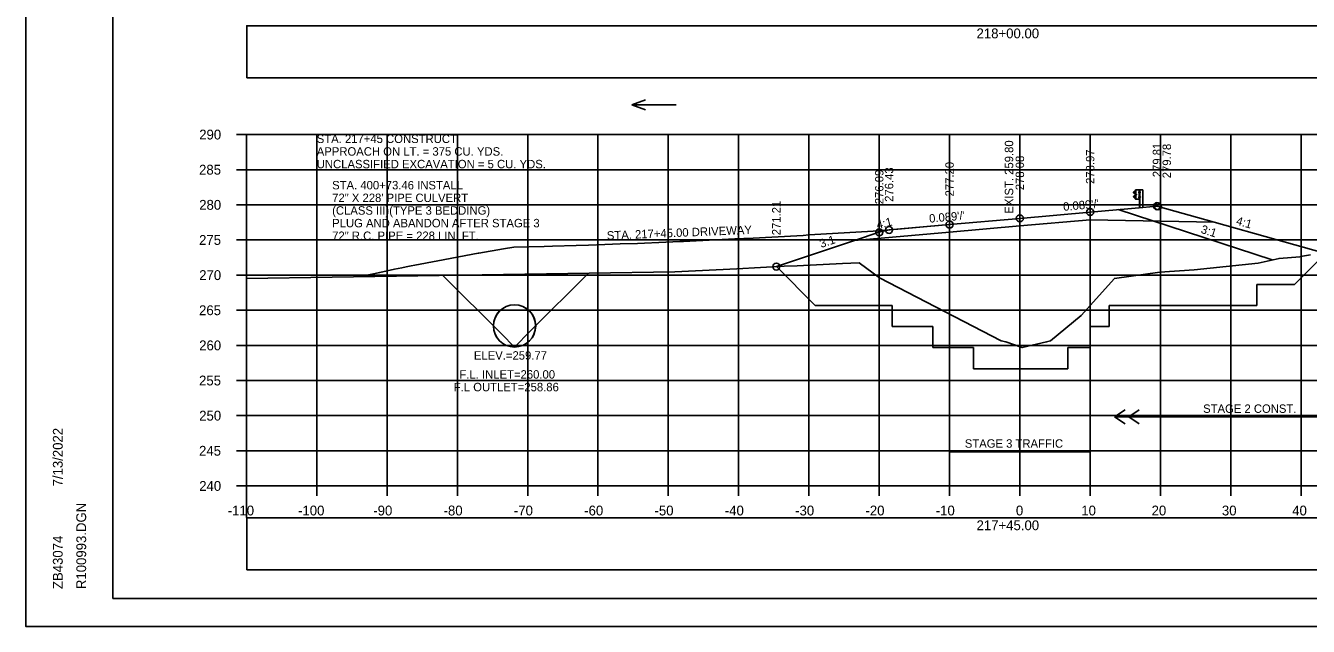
# Model space of a CAD drawing. Extents: x 4667 to 1632277, y -2100 to 724501.
# Drawn here: x 5635.8 to 5818.2, y -1110.4 to -1024.9 of the extents above; entities that cross this region are included whole.
import ezdxf

# ---------------------------------------------------------------- set-up
doc = ezdxf.new("R2010")
doc.units = 0
for name, color, linetype in [('R_Alt Surface', 7, 'Continuous'), ('R_Axis', 7, 'Continuous'), ('R_Axis Annot', 7, 'Continuous'), ('R_Border', 7, 'Continuous'), ('R_Draft', 7, 'Continuous'), ('R_Drive', 7, 'Continuous'), ('R_Exist Surface', 7, 'Continuous'), ('R_Fin Surface', 7, 'Continuous'), ('R_Fin Surface Annot', 7, 'Continuous'), ('R_Grid', 7, 'Continuous'), ('R_No Plot', 7, 'Continuous'), ('R_Proposed CofA', 7, 'Continuous'), ('R_ROW', 7, 'Continuous'), ('R_Temp Easement', 7, 'Continuous'), ('R_Water', 7, 'Continuous'), ('R_Water Annot', 7, 'Continuous'), ('R_Xsect Elev', 7, 'Continuous')]:
    doc.layers.add(name, color=color, linetype=linetype)

msp = doc.modelspace()

# ---------------------------------------------------------------- linework, layer by layer
at = {"layer": 'R_Alt Surface'}
msp.add_lwpolyline([(5753.67, -1055.51), (5767.18, -1054.32), (5777.18, -1053.43), (5787.18, -1052.54), (5804.84, -1052.9)], dxfattribs=at)
at = {"layer": 'R_Axis'}
for p, q in [((5665.78, -1040.43), (5667.18, -1040.43)), ((5667.18, -1090.43), (5667.18, -1040.43)), ((5665.78, -1045.43), (5667.18, -1045.43)), ((5665.78, -1050.43), (5667.18, -1050.43)), ((5665.78, -1055.43), (5667.18, -1055.43)), ((5665.78, -1060.43), (5667.18, -1060.43)), ((5665.78, -1065.43), (5667.18, -1065.43)), ((5665.78, -1070.43), (5667.18, -1070.43)), ((5665.78, -1075.43), (5667.18, -1075.43)), ((5665.78, -1080.43), (5667.18, -1080.43)), ((5665.78, -1085.43), (5667.18, -1085.43)), ((5665.78, -1090.43), (5667.18, -1090.43)), ((5667.18, -1090.43), (5947.18, -1090.43)), ((5667.18, -1091.83), (5667.18, -1090.43)), ((5677.18, -1091.83), (5677.18, -1090.43)), ((5687.18, -1091.83), (5687.18, -1090.43)), ((5697.18, -1091.83), (5697.18, -1090.43)), ((5707.18, -1091.83), (5707.18, -1090.43)), ((5717.18, -1091.83), (5717.18, -1090.43)), ((5727.18, -1091.83), (5727.18, -1090.43)), ((5737.18, -1091.83), (5737.18, -1090.43)), ((5747.18, -1091.83), (5747.18, -1090.43)), ((5757.18, -1091.83), (5757.18, -1090.43)), ((5767.18, -1091.83), (5767.18, -1090.43)), ((5777.18, -1091.83), (5777.18, -1090.43)), ((5787.18, -1091.83), (5787.18, -1090.43)), ((5797.18, -1091.83), (5797.18, -1090.43)), ((5807.18, -1091.83), (5807.18, -1090.43)), ((5817.18, -1091.83), (5817.18, -1090.43))]:
    msp.add_line(p, q, dxfattribs=at)
at = {"layer": 'R_Border'}
for p, q in [((5648.18, -1106.43), (5648.18, -900.97)), ((5648.18, -1106.43), (5648.18, -1106.43)), ((5964.36, -1106.43), (5648.18, -1106.43))]:
    msp.add_line(p, q, dxfattribs=at)
at = {"layer": 'R_Draft'}
for p, q in [((5793.39, -1048.6), (5793.52, -1048.49)), ((5793.56, -1048.85), (5793.39, -1048.74)), ((5793.4, -1048.61), (5793.53, -1048.51)), ((5793.57, -1048.82), (5793.4, -1048.72)), ((5793.52, -1048.49), (5793.63, -1048.43)), ((5793.53, -1048.51), (5793.62, -1048.46)), ((5793.6, -1049.03), (5793.6, -1048.89)), ((5793.62, -1049.02), (5793.62, -1048.89)), ((5793.66, -1049.64), (5793.66, -1048.28)), ((5793.67, -1049.03), (5793.67, -1048.9)), ((5793.67, -1048.9), (5793.72, -1048.9)), ((5793.67, -1048.93), (5793.72, -1048.93)), ((5793.67, -1049), (5793.72, -1049)), ((5793.67, -1049), (5793.72, -1049)), ((5793.73, -1049.01), (5793.73, -1048.92)), ((5794.15, -1048.58), (5794.1, -1048.58)), ((5794.1, -1048.58), (5794.1, -1048.71)), ((5794.1, -1048.65), (5794.16, -1048.65)), ((5794.15, -1048.71), (5794.1, -1048.71)), ((5794.16, -1048.28), (5794.17, -1048.28)), ((5794.16, -1048.28), (5794.23, -1048.28)), ((5794.19, -1050.79), (5794.19, -1048.28)), ((5794.23, -1048.7), (5794.23, -1048.58)), ((5794.23, -1048.58), (5794.28, -1048.58)), ((5794.23, -1048.61), (5794.28, -1048.61)), ((5794.23, -1048.67), (5794.27, -1048.67)), ((5794.23, -1048.67), (5794.28, -1048.67)), ((5794.23, -1048.7), (5794.28, -1048.7)), ((5794.28, -1048.69), (5794.28, -1048.59)), ((5794.65, -1048.28), (5794.65, -1050.79)), ((5794.68, -1048.28), (5794.68, -1050.79)), ((5793.51, -1049.44), (5793.38, -1049.33)), ((5793.52, -1049.43), (5793.4, -1049.32)), ((5793.41, -1049.18), (5793.57, -1049.08)), ((5793.42, -1049.2), (5793.58, -1049.1)), ((5793.62, -1049.5), (5793.51, -1049.44)), ((5793.63, -1049.48), (5793.52, -1049.43)), ((5793.67, -1049.03), (5793.72, -1049.03)), ((5794.1, -1049.39), (5794.1, -1049.27)), ((5794.1, -1049.27), (5794.15, -1049.27)), ((5794.1, -1049.33), (5794.16, -1049.33)), ((5794.1, -1049.39), (5794.15, -1049.39)), ((5794.16, -1049.64), (5794.19, -1049.64)), ((5794.24, -1049.39), (5794.24, -1049.27)), ((5794.24, -1049.27), (5794.29, -1049.27)), ((5794.24, -1049.3), (5794.29, -1049.3)), ((5794.24, -1049.36), (5794.28, -1049.36)), ((5794.24, -1049.36), (5794.29, -1049.36)), ((5794.24, -1049.39), (5794.29, -1049.39)), ((5794.29, -1049.38), (5794.29, -1049.28))]:
    msp.add_line(p, q, dxfattribs=at)
for points in [[(5793.63, -1048.28), (5793.64, -1049.64), (5794.16, -1049.64), (5794.16, -1048.28)], [(5793.67, -1048.88), (5793.67, -1049.05), (5793.66, -1049.05), (5793.66, -1048.88)], [(5793.73, -1048.93), (5793.73, -1048.99), (5793.76, -1048.99), (5793.76, -1048.93)], [(5794.1, -1048.58), (5794.1, -1048.71), (5794.16, -1048.71), (5794.16, -1048.58)], [(5794.23, -1048.56), (5794.23, -1048.73), (5794.22, -1048.73), (5794.22, -1048.56)], [(5794.29, -1048.61), (5794.29, -1048.67), (5794.31, -1048.67), (5794.31, -1048.61)], [(5794.1, -1049.27), (5794.1, -1049.39), (5794.16, -1049.39), (5794.16, -1049.27)], [(5794.24, -1049.25), (5794.24, -1049.42), (5794.23, -1049.42), (5794.23, -1049.25)], [(5794.3, -1049.3), (5794.3, -1049.36), (5794.32, -1049.36), (5794.32, -1049.3)]]:
    msp.add_lwpolyline(points, close=True, dxfattribs=at)
msp.add_lwpolyline([(5794.68, -1048.28), (5794.23, -1048.28), (5794.23, -1050.79)], dxfattribs=at)
for centre, radius, start, end in [((5793.43, -1048.67), 0.0856, 122.0217, 240.7501), ((5793.43, -1048.67), 0.062, 122.0217, 240.7501), ((5793.53, -1048.9), 0.0622, 4.9556, 61.894), ((5793.6, -1048.97), 0.0453, 93.9303, 257.0446), ((5793.53, -1048.9), 0.0865, 4.9556, 61.894), ((5793.71, -1048.92), 0.022, 317.7756, 45.4255), ((5793.64, -1048.96), 0.0922, 339.7423, 20.2577), ((5793.7, -1049.01), 0.025, 323.3766, 39.0666), ((5794.26, -1048.59), 0.022, 317.7756, 45.4255), ((5794.19, -1048.64), 0.0922, 339.7423, 20.2577), ((5794.26, -1048.69), 0.025, 323.3766, 39.0666), ((5793.47, -1049.27), 0.109, 120.88, 214.7816), ((5793.47, -1049.27), 0.0854, 120.88, 214.7816), ((5793.55, -1049.03), 0.0462, 293.1464, 8.2196), ((5793.55, -1049.03), 0.0703, 293.1464, 8.2196), ((5794.27, -1049.28), 0.022, 317.7756, 45.4255), ((5794.2, -1049.33), 0.0922, 339.7423, 20.2577), ((5794.27, -1049.38), 0.025, 323.3766, 39.0666)]:
    msp.add_arc(centre, radius, start, end, dxfattribs=at)
at = {"layer": 'R_Drive'}
msp.add_lwpolyline([(5683.38, -1060.65), (5686.14, -1060.05), (5688.22, -1059.6), (5689.3, -1059.38), (5689.89, -1059.27), (5690.59, -1059.13), (5691.11, -1059.03), (5694.4, -1058.41), (5700.12, -1057.33), (5700.15, -1057.33), (5700.25, -1057.31), (5703.73, -1056.7), (5705.19, -1056.46), (5709.54, -1056.35), (5710.72, -1056.31), (5714.09, -1056.21), (5715.82, -1056.16), (5718.17, -1056.08), (5720.35, -1056), (5722.79, -1055.91), (5726.81, -1055.75), (5728.81, -1055.66), (5729.34, -1055.64), (5736.62, -1055.29), (5737.14, -1055.27), (5737.19, -1055.27), (5737.93, -1055.23), (5738.33, -1055.21), (5746.34, -1054.77), (5747.18, -1054.72), (5748, -1054.67), (5757.18, -1054.12), (5767.18, -1053.23)], dxfattribs=at)
at = {"layer": 'R_Exist Surface'}
msp.add_lwpolyline([(5667.18, -1060.9), (5728.1, -1059.97), (5736.91, -1059.52), (5743.68, -1059.16), (5745.51, -1059.12), (5751.98, -1058.76), (5754.34, -1058.66), (5757.24, -1060.81), (5774.53, -1069.78), (5775.18, -1069.94), (5777.52, -1070.75), (5780.99, -1069.94), (5781.53, -1069.78), (5785.88, -1066.19), (5790.64, -1060.89), (5797.11, -1060.03), (5801.96, -1059.68), (5811.06, -1058.73), (5814.05, -1058.05), (5817.02, -1057.81), (5817.39, -1057.73), (5818.54, -1057.53)], dxfattribs=at)
at = {"layer": 'R_Fin Surface'}
msp.add_lwpolyline([(5742.55, -1059.22), (5753.67, -1055.51), (5757.18, -1054.34), (5758.58, -1054), (5767.18, -1053.23), (5777.18, -1052.35), (5787.18, -1051.46), (5794.68, -1050.79), (5796.68, -1050.62), (5796.84, -1050.65), (5804.84, -1052.9), (5813.57, -1055.34), (5820.2, -1057.19), (5836.48, -1062.63), (5841.23, -1064.21), (5841.87, -1064.42), (5845.62, -1065.68), (5849.97, -1067.12), (5850.83, -1067.41), (5861.41, -1070.93), (5896.41, -1070.93), (5930.91, -1059.43)], dxfattribs=at)
at = {"layer": 'R_Grid'}
for p, q in [((5667.18, -1040.43), (5947.18, -1040.43)), ((5667.18, -1090.43), (5667.18, -1040.43)), ((5677.18, -1090.43), (5677.18, -1040.43)), ((5687.18, -1090.43), (5687.18, -1040.43)), ((5697.18, -1090.43), (5697.18, -1040.43)), ((5707.18, -1090.43), (5707.18, -1040.43)), ((5717.18, -1090.43), (5717.18, -1040.43)), ((5727.18, -1090.43), (5727.18, -1040.43)), ((5737.18, -1090.43), (5737.18, -1040.43)), ((5747.18, -1090.43), (5747.18, -1040.43)), ((5757.18, -1090.43), (5757.18, -1040.43)), ((5767.18, -1090.43), (5767.18, -1040.43)), ((5777.18, -1090.43), (5777.18, -1040.43)), ((5787.18, -1090.43), (5787.18, -1040.43)), ((5797.18, -1090.43), (5797.18, -1040.43)), ((5807.18, -1090.43), (5807.18, -1040.43)), ((5817.18, -1090.43), (5817.18, -1040.43)), ((5667.18, -1045.43), (5947.18, -1045.43)), ((5667.18, -1050.43), (5947.18, -1050.43)), ((5667.18, -1055.43), (5947.18, -1055.43)), ((5667.18, -1060.43), (5947.18, -1060.43)), ((5667.18, -1065.43), (5947.18, -1065.43)), ((5667.18, -1070.43), (5947.18, -1070.43)), ((5667.18, -1075.43), (5947.18, -1075.43)), ((5667.18, -1080.43), (5947.18, -1080.43)), ((5667.18, -1085.43), (5947.18, -1085.43)), ((5667.18, -1090.43), (5947.18, -1090.43))]:
    msp.add_line(p, q, dxfattribs=at)
at = {"layer": 'R_No Plot'}
for p, q in [((5791.18, -1051.1), (5813.07, -1058.27)), ((5667.18, -1091.83), (5667.18, -1094.9)), ((5635.78, -1110.41), (5969.12, -1110.41))]:
    msp.add_line(p, q, dxfattribs=at)
for points in [[(5635.78, -897.08), (5969.12, -897.08), (5969.12, -1110.41), (5635.78, -1110.41)], [(5882.1, -900.97), (5901.72, -900.97), (5901.72, -910.85), (5917.84, -910.85), (5941.04, -910.85), (5941.04, -935.18), (5964.36, -935.18), (5964.36, -1106.43), (5648.18, -1106.43), (5648.18, -900.97)]]:
    msp.add_lwpolyline(points, close=True, dxfattribs=at)
msp.add_lwpolyline([(5695.12, -1060.48), (5703.44, -1068.8), (5705.31, -1070.66), (5707.54, -1068.42), (5715.81, -1060.16)], dxfattribs=at)
for centre, radius in [((5796.68, -1050.62), 0.5), ((5796.84, -1050.65), 0.5), ((5777.18, -1052.35), 0.5), ((5787.18, -1051.46), 0.5), ((5757.18, -1054.34), 0.5), ((5758.58, -1054), 0.5), ((5767.18, -1053.23), 0.5), ((5742.55, -1059.22), 0.5), ((5705.31, -1067.66), 3.01)]:
    msp.add_circle(centre, radius, dxfattribs=at)
at = {"layer": 'R_Proposed CofA'}
for p, q in [((5790.66, -1080.6), (5792.16, -1079.6)), ((5792.66, -1080.6), (5794.16, -1079.6)), ((5790.66, -1080.6), (5792.16, -1081.6)), ((5792.66, -1080.6), (5794.16, -1081.6))]:
    msp.add_line(p, q, dxfattribs=at)
for points in [[(5667.23, -1032.37), (5947.13, -1032.37), (5947.13, -1024.95), (5667.23, -1024.95)], [(5667.23, -1102.37), (5947.13, -1102.37), (5947.13, -1094.95), (5667.23, -1094.95)]]:
    msp.add_lwpolyline(points, close=True, dxfattribs=at)
at = {"layer": 'R_ROW'}
for p, q in [((5820.66, -1057.35), (5816.26, -1061.75)), ((5742.55, -1059.22), (5748.08, -1064.75)), ((5810.89, -1061.75), (5816.26, -1061.75)), ((5810.89, -1061.75), (5810.89, -1064.75)), ((5759.04, -1064.75), (5748.08, -1064.75)), ((5759.04, -1067.75), (5759.04, -1064.75)), ((5789.87, -1064.75), (5789.87, -1067.75)), ((5789.87, -1064.75), (5810.89, -1064.75)), ((5764.82, -1067.75), (5759.04, -1067.75)), ((5764.82, -1070.75), (5764.82, -1067.75)), ((5787.17, -1067.75), (5787.17, -1070.75)), ((5787.17, -1067.75), (5789.87, -1067.75)), ((5764.82, -1070.75), (5770.61, -1070.75)), ((5770.61, -1073.75), (5770.61, -1070.75)), ((5783.99, -1070.75), (5783.99, -1073.75)), ((5783.99, -1070.75), (5787.17, -1070.75)), ((5783.99, -1073.75), (5770.61, -1073.75))]:
    msp.add_line(p, q, dxfattribs=at)
at = {"layer": 'R_Temp Easement'}
for p, q in [((5820.66, -1080.6), (5790.66, -1080.6)), ((5767.18, -1087.6), (5767.18, -1083.6)), ((5787.18, -1087.6), (5787.18, -1083.6)), ((5787.18, -1085.6), (5767.18, -1085.6))]:
    msp.add_line(p, q, dxfattribs=at)
at = {"layer": 'R_Water'}
msp.add_circle((5705.31, -1067.66), 3, dxfattribs=at)
at = {"layer": 'R_Water Annot'}
for p, q in [((5722.01, -1036.2), (5723.94, -1035.5)), ((5728.3, -1036.2), (5722.01, -1036.2)), ((5722.01, -1036.2), (5723.94, -1036.9))]:
    msp.add_line(p, q, dxfattribs=at)

# ---------------------------------------------------------------- texts
at = {"layer": 'R_Axis Annot'}
for s, p in [('218+00.00', (5771.02, -1026.73)), ('290', (5660.46, -1041.13)), ('285', (5660.44, -1046.13)), ('280', (5660.46, -1051.13)), ('275', (5660.44, -1056.13)), ('270', (5660.46, -1061.13)), ('265', (5660.44, -1066.13)), ('260', (5660.46, -1071.13)), ('255', (5660.44, -1076.13)), ('250', (5660.46, -1081.13)), ('245', (5660.44, -1086.13)), ('240', (5660.46, -1091.13)), ('-110', (5664.52, -1094.63)), ('-100', (5674.52, -1094.63)), ('-90', (5685.22, -1094.63)), ('-80', (5695.22, -1094.63)), ('-70', (5705.22, -1094.63)), ('-60', (5715.22, -1094.63)), ('-50', (5725.22, -1094.63)), ('-40', (5735.22, -1094.63)), ('-30', (5745.22, -1094.63)), ('-20', (5755.22, -1094.63)), ('-10', (5765.22, -1094.63)), ('0', (5776.62, -1094.63)), ('10', (5785.92, -1094.63)), ('20', (5795.92, -1094.63)), ('30', (5805.92, -1094.63)), ('40', (5815.92, -1094.63)), ('217+45.00', (5771.02, -1096.73))]:
    msp.add_text(s, height=1.4, dxfattribs=at).set_placement(p)
at = {"layer": 'R_Border'}
for s, p in [('7/13/2022', (5641.05, -1090.5)), ('R100993.DGN', (5644.38, -1105.11)), ('ZB43074', (5641.05, -1105.11))]:
    msp.add_text(s, height=1.4, rotation=90, dxfattribs=at).set_placement(p)
at = {"layer": 'R_Drive'}
msp.add_text('STA. 217+45.00 DRIVEWAY', height=1.2, rotation=2.3161, dxfattribs=at).set_placement((5718.46, -1055.4))
at = {"layer": 'R_Fin Surface Annot'}
for s, rotation, p in [('279.81', 90, (5797.28, -1046.5)), ('278.08', 90, (5777.78, -1048.35)), ('278.97', 90, (5787.78, -1047.46)), ('279.78', 90, (5798.68, -1046.65)), ('276.43', 90, (5759.18, -1050)), ('277.20', 90, (5767.78, -1049.23)), ('276.09', 90, (5757.78, -1050.34)), ('271.21', 90, (5743.14, -1054.76)), ("0.089'/'", 5.0688, (5783.39, -1051.29)), ('4:1', 14.0362, (5756.95, -1053.89)), ("0.089'/'", 5.0688, (5764.33, -1052.98)), ('4:1', 344.3648, (5807.85, -1053.22)), ('3:1', 18.4349, (5748.92, -1056.57))]:
    msp.add_text(s, height=1.2, rotation=rotation, dxfattribs=at).set_placement(p)
at = {"layer": 'R_No Plot'}
msp.add_text('3:1', height=1.2, rotation=342.3902, dxfattribs=at).set_placement((5802.83, -1054.4))
at = {"layer": 'R_Temp Easement'}
msp.add_text('EXIST. 259.80', height=1.2, rotation=90, dxfattribs=at).set_placement((5776.24, -1051.69))
for s, p in [('STAGE 2 CONST.', (5803.25, -1080.03)), ('STAGE 3 TRAFFIC', (5769.35, -1084.99))]:
    msp.add_text(s, height=1.1985, dxfattribs=at).set_placement(p)
at = {"layer": 'R_Water Annot'}
for s, p in [('STA. 217+45 CONSTRUCT ', (5677.18, -1041.63)), ('APPROACH ON LT. = 375 CU. YDS.', (5677.18, -1043.43)), ('UNCLASSIFIED EXCAVATION = 5 CU. YDS.', (5677.18, -1045.23)), ('STA. 400+73.46 INSTALL ', (5679.37, -1048.23)), ('72" X 228\' PIPE CULVERT', (5679.37, -1050.03)), ('(CLASS III)(TYPE 3 BEDDING)', (5679.37, -1051.83)), ('PLUG AND ABANDON AFTER STAGE 3', (5679.37, -1053.63)), ('72" R.C. PIPE = 228 LIN. FT.', (5679.37, -1055.43)), ('F.L. INLET=260.00', (5697.47, -1075.16)), ('F.L OUTLET=258.86', (5696.67, -1076.96))]:
    msp.add_text(s, height=1.2, dxfattribs=at).set_placement(p)
at = {"layer": 'R_Xsect Elev'}
msp.add_text('ELEV.=259.77', height=1.2, dxfattribs=at).set_placement((5699.53, -1072.46))

doc.saveas('drawing.dxf')
